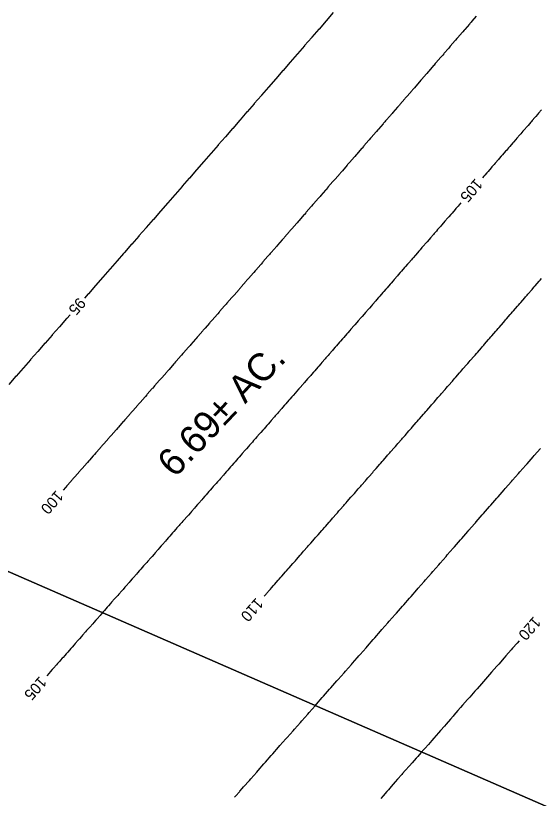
# Model space of a CAD drawing. Extents: x 1752788 to 1754108, y 472767 to 474963.
# Drawn here: x 1753161.2 to 1753208.6, y 473792.4 to 473863.1 of the extents above; entities that cross this region are included whole.
import ezdxf

# ---------------------------------------------------------------- set-up
doc = ezdxf.new("R2010")
doc.units = 0
for name, color, linetype in [('CLRLGD4', 7, 'Continuous'), ('D_Drainage_Culvert', 7, 'Continuous'), ('D_Roadway_Centerline', 7, 'Continuous'), ('Default', 7, 'Continuous'), ('S_Contours_Major', 7, 'Continuous')]:
    doc.layers.add(name, color=color, linetype=linetype)

msp = doc.modelspace()

# ---------------------------------------------------------------- linework, layer by layer
at = {"layer": 'D_Drainage_Culvert'}
msp.add_line((1753148.958, 473817.925), (1753295.6, 473753.923), dxfattribs=at)
at = {"layer": 'D_Roadway_Centerline'}
msp.add_arc((1748084.974, 477769.754), 6500, 316.3419444, 334.4169444, dxfattribs=at)
at = {"layer": 'Default'}
msp.add_line((1753295.6, 473753.923), (1753145.826, 473819.295), dxfattribs=at)
at = {"layer": 'S_Contours_Major'}
for points in [[(1753189.858, 473863.372), (1753189.219, 473862.634), (1753189.209, 473862.623), (1753188.57, 473861.886), (1753188.56, 473861.875), (1753187.921, 473861.137), (1753187.911, 473861.126), (1753187.272, 473860.388), (1753187.262, 473860.377), (1753186.623, 473859.64), (1753186.613, 473859.629), (1753185.973, 473858.892), (1753185.963, 473858.88), (1753185.324, 473858.143), (1753185.314, 473858.132), (1753184.675, 473857.395), (1753184.664, 473857.384), (1753184.025, 473856.647), (1753184.015, 473856.635), (1753183.375, 473855.899), (1753183.365, 473855.887), (1753182.725, 473855.151), (1753182.715, 473855.139), (1753182.076, 473854.404), (1753182.065, 473854.392), (1753181.454, 473853.689), (1753181.414, 473853.643), (1753180.775, 473852.909), (1753180.764, 473852.896), (1753180.125, 473852.161), (1753180.114, 473852.149), (1753179.475, 473851.414), (1753179.464, 473851.401), (1753178.824, 473850.667), (1753178.813, 473850.654), (1753178.174, 473849.92), (1753178.163, 473849.907), (1753177.523, 473849.173), (1753177.512, 473849.16), (1753176.872, 473848.426), (1753176.861, 473848.414), (1753176.222, 473847.679), (1753176.211, 473847.667), (1753175.571, 473846.933), (1753175.56, 473846.92), (1753174.919, 473846.186), (1753174.908, 473846.174), (1753174.268, 473845.44), (1753174.257, 473845.427), (1753173.617, 473844.694), (1753173.606, 473844.681), (1753172.966, 473843.948), (1753172.955, 473843.935), (1753172.314, 473843.201), (1753172.303, 473843.189), (1753171.662, 473842.456), (1753171.651, 473842.443), (1753171.012, 473841.711), (1753170.932, 473841.62), (1753170.359, 473840.964), (1753170.348, 473840.951), (1753169.707, 473840.218), (1753169.696, 473840.206), (1753169.055, 473839.473), (1753169.044, 473839.46), (1753168.403, 473838.727), (1753168.392, 473838.715), (1753167.75, 473837.982), (1753167.739, 473837.97), (1753167.402, 473837.585)], [(1753202.76, 473863.031), (1753202.375, 473862.585), (1753202.317, 473862.517), (1753202.2, 473862.382), (1753202.161, 473862.337), (1753201.726, 473861.834), (1753201.668, 473861.767), (1753201.551, 473861.632), (1753201.512, 473861.587), (1753201.077, 473861.083), (1753201.019, 473861.016), (1753200.902, 473860.881), (1753200.863, 473860.836), (1753200.424, 473860.329), (1753200.282, 473860.164), (1753200.25, 473860.127), (1753199.873, 473859.691), (1753199.844, 473859.658), (1753199.736, 473859.533), (1753199.604, 473859.38), (1753199.565, 473859.335), (1753199.13, 473858.832), (1753199.071, 473858.765), (1753198.955, 473858.63), (1753198.916, 473858.585), (1753198.48, 473858.081), (1753198.422, 473858.014), (1753198.306, 473857.88), (1753198.267, 473857.835), (1753197.831, 473857.331), (1753197.772, 473857.264), (1753197.656, 473857.13), (1753197.618, 473857.085), (1753197.181, 473856.581), (1753197.123, 473856.514), (1753197.007, 473856.38), (1753196.968, 473856.335), (1753196.531, 473855.831), (1753196.473, 473855.764), (1753196.357, 473855.63), (1753196.318, 473855.586), (1753195.881, 473855.081), (1753195.823, 473855.014), (1753195.707, 473854.88), (1753195.669, 473854.836), (1753195.231, 473854.332), (1753195.173, 473854.265), (1753195.058, 473854.131), (1753195.019, 473854.086), (1753194.581, 473853.582), (1753194.523, 473853.515), (1753194.408, 473853.381), (1753194.369, 473853.337), (1753193.931, 473852.832), (1753193.873, 473852.766), (1753193.757, 473852.632), (1753193.719, 473852.588), (1753193.281, 473852.083), (1753193.223, 473852.016), (1753193.107, 473851.883), (1753193.069, 473851.838), (1753192.63, 473851.334), (1753192.573, 473851.267), (1753192.457, 473851.134), (1753192.418, 473851.089), (1753191.98, 473850.584), (1753191.922, 473850.518), (1753191.807, 473850.385), (1753191.768, 473850.34), (1753191.329, 473849.835), (1753191.272, 473849.769), (1753191.156, 473849.636), (1753191.118, 473849.591), (1753190.679, 473849.086), (1753190.621, 473849.02), (1753190.505, 473848.887), (1753190.467, 473848.842), (1753190.027, 473848.336), (1753189.861, 473848.145), (1753189.824, 473848.102), (1753189.382, 473847.595), (1753189.353, 473847.561), (1753189.204, 473847.389), (1753189.165, 473847.345), (1753188.726, 473846.84), (1753188.668, 473846.773), (1753188.553, 473846.641), (1753188.514, 473846.596), (1753188.075, 473846.091), (1753188.017, 473846.025), (1753187.902, 473845.892), (1753187.863, 473845.848), (1753187.423, 473845.343), (1753187.366, 473845.276), (1753187.251, 473845.144), (1753187.212, 473845.1), (1753186.772, 473844.594), (1753186.714, 473844.528), (1753186.599, 473844.396), (1753186.561, 473844.352), (1753186.12, 473843.846), (1753186.063, 473843.78), (1753185.948, 473843.648), (1753185.91, 473843.604), (1753185.469, 473843.098), (1753185.411, 473843.032), (1753185.297, 473842.9), (1753185.258, 473842.856), (1753184.817, 473842.35), (1753184.76, 473842.284), (1753184.645, 473842.152), (1753184.607, 473842.108), (1753184.165, 473841.602), (1753184.108, 473841.536), (1753183.994, 473841.405), (1753183.955, 473841.361), (1753183.513, 473840.854), (1753183.456, 473840.788), (1753183.342, 473840.657), (1753183.304, 473840.613), (1753182.861, 473840.106), (1753182.804, 473840.041), (1753182.69, 473839.91), (1753182.652, 473839.866), (1753182.209, 473839.359), (1753182.152, 473839.293), (1753182.038, 473839.162), (1753182, 473839.119), (1753181.557, 473838.611), (1753181.5, 473838.546), (1753181.386, 473838.415), (1753181.348, 473838.371), (1753180.904, 473837.864), (1753180.848, 473837.798), (1753180.734, 473837.668), (1753180.696, 473837.624), (1753180.252, 473837.116), (1753180.195, 473837.051), (1753180.081, 473836.921), (1753180.043, 473836.877), (1753179.599, 473836.369), (1753179.543, 473836.304), (1753179.429, 473836.174), (1753179.391, 473836.13), (1753178.924, 473835.596), (1753178.845, 473835.506), (1753178.723, 473835.366), (1753178.689, 473835.328), (1753178.294, 473834.875), (1753178.237, 473834.81), (1753178.124, 473834.68), (1753178.086, 473834.637), (1753177.641, 473834.128), (1753177.584, 473834.063), (1753177.471, 473833.934), (1753177.433, 473833.89), (1753176.988, 473833.381), (1753176.931, 473833.317), (1753176.818, 473833.187), (1753176.78, 473833.144), (1753176.335, 473832.635), (1753176.278, 473832.57), (1753176.165, 473832.441), (1753176.127, 473832.398), (1753175.682, 473831.888), (1753175.625, 473831.824), (1753175.512, 473831.694), (1753175.474, 473831.651), (1753175.028, 473831.142), (1753174.972, 473831.077), (1753174.859, 473830.948), (1753174.821, 473830.905), (1753174.375, 473830.395), (1753174.318, 473830.331), (1753174.206, 473830.202), (1753174.168, 473830.159), (1753173.721, 473829.649), (1753173.665, 473829.585), (1753173.552, 473829.456), (1753173.515, 473829.414), (1753173.067, 473828.903), (1753173.011, 473828.839), (1753172.899, 473828.711), (1753172.861, 473828.668), (1753172.414, 473828.157), (1753172.357, 473828.093), (1753172.245, 473827.965), (1753172.208, 473827.922), (1753171.76, 473827.411), (1753171.704, 473827.347), (1753171.592, 473827.219), (1753171.554, 473827.177), (1753171.106, 473826.665), (1753171.05, 473826.601), (1753170.938, 473826.474), (1753170.9, 473826.431), (1753170.452, 473825.92), (1753170.396, 473825.856), (1753170.284, 473825.728), (1753170.247, 473825.686), (1753169.797, 473825.174), (1753169.741, 473825.11), (1753169.63, 473824.983), (1753169.593, 473824.941), (1753169.143, 473824.429), (1753169.087, 473824.365), (1753168.976, 473824.238), (1753168.939, 473824.196), (1753168.47, 473823.662), (1753168.423, 473823.609), (1753168.291, 473823.458), (1753168.18, 473823.332), (1753167.834, 473822.938), (1753167.778, 473822.875), (1753167.667, 473822.748), (1753167.63, 473822.706), (1753167.179, 473822.193), (1753167.124, 473822.13), (1753167.013, 473822.003), (1753166.976, 473821.961), (1753166.524, 473821.448), (1753166.469, 473821.385), (1753166.358, 473821.258), (1753166.321, 473821.216), (1753165.87, 473820.703), (1753165.814, 473820.64), (1753165.703, 473820.514), (1753165.667, 473820.472), (1753165.458, 473820.234)], [(1753208.664, 473854.597), (1753208.385, 473854.274), (1753208.293, 473854.167), (1753208.139, 473853.99), (1753208.047, 473853.883), (1753207.818, 473853.618), (1753207.755, 473853.545), (1753207.688, 473853.468), (1753207.44, 473853.181), (1753207.365, 473853.094), (1753207.091, 473852.778), (1753206.978, 473852.648), (1753206.79, 473852.43), (1753206.715, 473852.343), (1753206.441, 473852.027), (1753206.328, 473851.896), (1753206.14, 473851.679), (1753206.065, 473851.592), (1753205.79, 473851.275), (1753205.678, 473851.145), (1753205.49, 473850.928), (1753205.415, 473850.841), (1753205.14, 473850.524), (1753205.027, 473850.394), (1753204.84, 473850.177), (1753204.765, 473850.09), (1753204.489, 473849.773), (1753204.377, 473849.643), (1753204.189, 473849.426), (1753204.114, 473849.34), (1753203.838, 473849.021), (1753203.726, 473848.892), (1753203.539, 473848.676), (1753203.464, 473848.589), (1753203.337, 473848.443)], [(1753201.38, 473846.186), (1753201.234, 473846.018), (1753201.122, 473845.889), (1753200.935, 473845.674), (1753200.861, 473845.588), (1753200.583, 473845.267), (1753200.471, 473845.139), (1753200.284, 473844.924), (1753200.21, 473844.838), (1753199.931, 473844.517), (1753199.819, 473844.388), (1753199.633, 473844.174), (1753199.559, 473844.088), (1753199.28, 473843.767), (1753199.168, 473843.638), (1753198.982, 473843.424), (1753198.907, 473843.338), (1753198.628, 473843.016), (1753198.516, 473842.888), (1753198.33, 473842.674), (1753198.256, 473842.588), (1753197.975, 473842.264), (1753197.868, 473842.141), (1753197.689, 473841.936), (1753197.582, 473841.813), (1753197.31, 473841.5), (1753197.284, 473841.469), (1753197.064, 473841.217), (1753196.99, 473841.132), (1753196.916, 473841.046), (1753196.672, 473840.766), (1753196.561, 473840.638), (1753196.375, 473840.425), (1753196.301, 473840.34), (1753196.02, 473840.016), (1753195.909, 473839.888), (1753195.724, 473839.676), (1753195.65, 473839.59), (1753195.368, 473839.267), (1753195.257, 473839.139), (1753195.072, 473838.926), (1753194.998, 473838.841), (1753194.715, 473838.517), (1753194.605, 473838.389), (1753194.42, 473838.177), (1753194.346, 473838.092), (1753194.063, 473837.767), (1753193.952, 473837.64), (1753193.768, 473837.428), (1753193.694, 473837.343), (1753193.41, 473837.018), (1753193.3, 473836.891), (1753193.115, 473836.679), (1753193.042, 473836.594), (1753192.758, 473836.269), (1753192.647, 473836.142), (1753192.463, 473835.93), (1753192.389, 473835.846), (1753192.105, 473835.519), (1753191.995, 473835.393), (1753191.811, 473835.182), (1753191.737, 473835.097), (1753191.452, 473834.77), (1753191.342, 473834.644), (1753191.158, 473834.433), (1753191.084, 473834.349), (1753190.799, 473834.021), (1753190.689, 473833.895), (1753190.505, 473833.684), (1753190.432, 473833.6), (1753190.146, 473833.272), (1753190.036, 473833.146), (1753189.852, 473832.936), (1753189.779, 473832.852), (1753189.493, 473832.524), (1753189.383, 473832.398), (1753189.2, 473832.188), (1753189.126, 473832.104), (1753188.839, 473831.775), (1753188.73, 473831.649), (1753188.547, 473831.439), (1753188.473, 473831.356), (1753188.186, 473831.026), (1753188.076, 473830.901), (1753187.893, 473830.691), (1753187.82, 473830.608), (1753187.532, 473830.278), (1753187.423, 473830.153), (1753187.24, 473829.943), (1753187.167, 473829.86), (1753187.131, 473829.818), (1753186.834, 473829.479), (1753186.763, 473829.398), (1753186.545, 473829.147), (1753186.447, 473829.035), (1753186.225, 473828.781), (1753186.116, 473828.656), (1753185.933, 473828.448), (1753185.86, 473828.364), (1753185.571, 473828.033), (1753185.462, 473827.908), (1753185.28, 473827.7), (1753185.207, 473827.617), (1753184.917, 473827.285), (1753184.808, 473827.161), (1753184.626, 473826.953), (1753184.553, 473826.869), (1753184.517, 473826.828), (1753184.263, 473826.537), (1753184.154, 473826.413), (1753183.972, 473826.205), (1753183.9, 473826.122), (1753183.863, 473826.081), (1753183.609, 473825.79), (1753183.5, 473825.665), (1753183.318, 473825.458), (1753183.246, 473825.375), (1753183.21, 473825.333), (1753182.954, 473825.042), (1753182.846, 473824.918), (1753182.664, 473824.711), (1753182.556, 473824.586), (1753182.3, 473824.294), (1753182.191, 473824.17), (1753182.01, 473823.963), (1753181.902, 473823.839), (1753181.645, 473823.547), (1753181.537, 473823.423), (1753181.356, 473823.217), (1753181.248, 473823.093), (1753180.991, 473822.799), (1753180.882, 473822.676), (1753180.702, 473822.47), (1753180.593, 473822.346), (1753180.336, 473822.052), (1753180.228, 473821.929), (1753180.047, 473821.723), (1753179.939, 473821.599), (1753179.681, 473821.305), (1753179.573, 473821.182), (1753179.393, 473820.976), (1753179.285, 473820.853), (1753179.026, 473820.558), (1753178.918, 473820.435), (1753178.738, 473820.23), (1753178.63, 473820.107), (1753178.371, 473819.811), (1753178.263, 473819.688), (1753178.083, 473819.483), (1753177.976, 473819.36), (1753177.716, 473819.064), (1753177.608, 473818.941), (1753177.429, 473818.737), (1753177.321, 473818.614), (1753177.061, 473818.318), (1753176.953, 473818.195), (1753176.774, 473817.991), (1753176.666, 473817.868), (1753176.369, 473817.53), (1753176.279, 473817.427), (1753176.181, 473817.316), (1753176.017, 473817.128), (1753175.936, 473817.037), (1753175.748, 473816.823), (1753175.645, 473816.705), (1753175.463, 473816.498), (1753175.356, 473816.376), (1753175.094, 473816.078), (1753174.987, 473815.956), (1753174.808, 473815.753), (1753174.701, 473815.631), (1753174.438, 473815.332), (1753174.331, 473815.21), (1753174.153, 473815.007), (1753174.046, 473814.885), (1753173.782, 473814.586), (1753173.675, 473814.464), (1753173.497, 473814.261), (1753173.39, 473814.139), (1753173.126, 473813.839), (1753173.02, 473813.718), (1753172.842, 473813.515), (1753172.735, 473813.394), (1753172.47, 473813.093), (1753172.364, 473812.972), (1753172.186, 473812.77), (1753172.079, 473812.649), (1753171.814, 473812.348), (1753171.708, 473812.226), (1753171.53, 473812.025), (1753171.423, 473811.903), (1753171.158, 473811.602), (1753171.051, 473811.481), (1753170.874, 473811.279), (1753170.768, 473811.158), (1753170.501, 473810.856), (1753170.395, 473810.735), (1753170.218, 473810.534), (1753170.112, 473810.413), (1753169.845, 473810.111), (1753169.739, 473809.99), (1753169.562, 473809.789), (1753169.456, 473809.669), (1753169.188, 473809.365), (1753169.082, 473809.245), (1753168.905, 473809.044), (1753168.799, 473808.924), (1753168.532, 473808.62), (1753168.426, 473808.5), (1753168.249, 473808.299), (1753168.143, 473808.179), (1753167.875, 473807.875), (1753167.769, 473807.755), (1753167.592, 473807.554), (1753167.487, 473807.434), (1753167.218, 473807.13), (1753167.112, 473807.01), (1753166.936, 473806.81), (1753166.83, 473806.69), (1753166.561, 473806.385), (1753166.455, 473806.265), (1753166.279, 473806.065), (1753166.173, 473805.945), (1753165.882, 473805.616), (1753165.742, 473805.456), (1753165.607, 473805.304), (1753165.458, 473805.135), (1753165.394, 473805.062), (1753165.239, 473804.887), (1753165.155, 473804.791), (1753164.964, 473804.575), (1753164.858, 473804.455), (1753164.589, 473804.151), (1753164.483, 473804.031), (1753164.307, 473803.831), (1753164.201, 473803.711), (1753163.987, 473803.468)], [(1753183.63, 473810.671), (1753183.656, 473810.7), (1753183.786, 473810.848), (1753183.829, 473810.897), (1753184.103, 473811.21), (1753184.176, 473811.293), (1753184.295, 473811.429), (1753184.471, 473811.629), (1753184.558, 473811.727), (1753184.896, 473812.113), (1753184.983, 473812.212), (1753185.127, 473812.376), (1753185.213, 473812.474), (1753185.552, 473812.861), (1753185.639, 473812.959), (1753185.782, 473813.123), (1753185.869, 473813.222), (1753186.209, 473813.609), (1753186.295, 473813.707), (1753186.438, 473813.871), (1753186.524, 473813.969), (1753186.865, 473814.357), (1753186.95, 473814.455), (1753187.094, 473814.618), (1753187.179, 473814.716), (1753187.521, 473815.106), (1753187.606, 473815.203), (1753187.749, 473815.366), (1753187.834, 473815.464), (1753188.176, 473815.854), (1753188.262, 473815.951), (1753188.404, 473816.114), (1753188.49, 473816.211), (1753188.832, 473816.602), (1753188.917, 473816.7), (1753189.059, 473816.862), (1753189.144, 473816.959), (1753189.488, 473817.351), (1753189.573, 473817.448), (1753189.714, 473817.61), (1753189.799, 473817.707), (1753190.143, 473818.1), (1753190.228, 473818.197), (1753190.369, 473818.358), (1753190.454, 473818.454), (1753190.799, 473818.849), (1753190.883, 473818.945), (1753191.024, 473819.106), (1753191.109, 473819.203), (1753191.454, 473819.597), (1753191.538, 473819.694), (1753191.679, 473819.854), (1753191.763, 473819.951), (1753192.109, 473820.347), (1753192.193, 473820.443), (1753192.333, 473820.603), (1753192.417, 473820.699), (1753192.764, 473821.096), (1753192.848, 473821.192), (1753192.988, 473821.351), (1753193.072, 473821.447), (1753193.419, 473821.845), (1753193.503, 473821.941), (1753193.642, 473822.1), (1753193.726, 473822.196), (1753194.077, 473822.598), (1753194.152, 473822.683), (1753194.276, 473822.825), (1753194.35, 473822.91), (1753194.693, 473823.303), (1753194.768, 473823.389), (1753194.951, 473823.598), (1753195.034, 473823.693), (1753195.384, 473824.093), (1753195.466, 473824.188), (1753195.605, 473824.347), (1753195.688, 473824.442), (1753196.038, 473824.843), (1753196.121, 473824.938), (1753196.259, 473825.096), (1753196.341, 473825.19), (1753196.692, 473825.593), (1753196.775, 473825.687), (1753196.913, 473825.845), (1753196.995, 473825.939), (1753197.347, 473826.343), (1753197.429, 473826.437), (1753197.566, 473826.594), (1753197.649, 473826.689), (1753198.001, 473827.093), (1753198.083, 473827.187), (1753198.22, 473827.344), (1753198.302, 473827.438), (1753198.655, 473827.843), (1753198.737, 473827.937), (1753198.873, 473828.093), (1753198.955, 473828.187), (1753199.309, 473828.593), (1753199.391, 473828.687), (1753199.527, 473828.843), (1753199.608, 473828.936), (1753199.963, 473829.343), (1753200.044, 473829.437), (1753200.18, 473829.592), (1753200.261, 473829.686), (1753200.617, 473830.094), (1753200.698, 473830.187), (1753200.833, 473830.342), (1753200.914, 473830.435), (1753201.27, 473830.844), (1753201.351, 473830.937), (1753201.486, 473831.092), (1753201.567, 473831.185), (1753201.924, 473831.595), (1753202.005, 473831.688), (1753202.139, 473831.842), (1753202.22, 473831.935), (1753202.577, 473832.346), (1753202.658, 473832.438), (1753202.792, 473832.592), (1753202.873, 473832.685), (1753203.231, 473833.097), (1753203.311, 473833.189), (1753203.445, 473833.343), (1753203.525, 473833.435), (1753203.884, 473833.848), (1753203.964, 473833.94), (1753204.097, 473834.093), (1753204.177, 473834.185), (1753204.537, 473834.599), (1753204.617, 473834.691), (1753204.75, 473834.844), (1753204.83, 473834.935), (1753205.219, 473835.383), (1753205.247, 473835.416), (1753205.421, 473835.616), (1753205.497, 473835.704), (1753205.843, 473836.101), (1753205.922, 473836.193), (1753206.055, 473836.345), (1753206.134, 473836.436), (1753206.496, 473836.853), (1753206.575, 473836.944), (1753206.707, 473837.096), (1753206.786, 473837.187), (1753207.148, 473837.604), (1753207.227, 473837.695), (1753207.359, 473837.847), (1753207.438, 473837.938), (1753207.801, 473838.356), (1753207.88, 473838.446), (1753208.011, 473838.598), (1753208.09, 473838.688), (1753208.453, 473839.107), (1753208.532, 473839.198), (1753208.663, 473839.349)], [(1753166.09, 473836.086), (1753165.793, 473835.747), (1753165.782, 473835.734), (1753165.14, 473835.002), (1753165.129, 473834.99), (1753164.487, 473834.257), (1753164.477, 473834.245), (1753163.834, 473833.513), (1753163.824, 473833.5), (1753163.181, 473832.768), (1753163.171, 473832.756), (1753162.528, 473832.024), (1753162.518, 473832.012), (1753161.875, 473831.279), (1753161.864, 473831.267), (1753161.221, 473830.535), (1753161.211, 473830.523), (1753160.567, 473829.79)], [(1753180.934, 473792.5), (1753180.97, 473792.541), (1753181.057, 473792.64), (1753181.38, 473793.006), (1753181.427, 473793.059), (1753181.637, 473793.297), (1753181.755, 473793.431), (1753182.283, 473794.03), (1753182.414, 473794.178), (1753182.942, 473794.777), (1753183.072, 473794.925), (1753183.601, 473795.525), (1753183.73, 473795.671), (1753184.259, 473796.272), (1753184.388, 473796.418), (1753184.918, 473797.02), (1753185.045, 473797.165), (1753185.577, 473797.768), (1753185.703, 473797.912), (1753186.235, 473798.516), (1753186.361, 473798.659), (1753186.893, 473799.264), (1753187.018, 473799.406), (1753187.552, 473800.012), (1753187.675, 473800.153), (1753188.21, 473800.761), (1753188.333, 473800.9), (1753188.868, 473801.509), (1753188.99, 473801.648), (1753189.526, 473802.258), (1753189.647, 473802.395), (1753190.184, 473803.006), (1753190.304, 473803.143), (1753190.841, 473803.755), (1753190.96, 473803.891), (1753191.502, 473804.507), (1753191.599, 473804.618), (1753192.008, 473805.084), (1753192.032, 473805.111), (1753192.18, 473805.28), (1753192.285, 473805.4), (1753192.814, 473806.002), (1753192.942, 473806.148), (1753193.471, 473806.751), (1753193.598, 473806.896), (1753194.128, 473807.5), (1753194.254, 473807.644), (1753194.785, 473808.25), (1753194.91, 473808.393), (1753195.442, 473808.999), (1753195.566, 473809.141), (1753196.099, 473809.749), (1753196.222, 473809.89), (1753196.755, 473810.499), (1753196.878, 473810.638), (1753197.412, 473811.249), (1753197.533, 473811.387), (1753198.068, 473811.999), (1753198.189, 473812.136), (1753198.725, 473812.749), (1753198.844, 473812.885), (1753199.381, 473813.499), (1753199.499, 473813.634), (1753200.037, 473814.249), (1753200.154, 473814.383), (1753200.693, 473814.999), (1753200.809, 473815.132), (1753201.349, 473815.75), (1753201.464, 473815.882), (1753202.006, 473816.502), (1753202.108, 473816.618), (1753202.604, 473817.186), (1753202.686, 473817.28), (1753202.774, 473817.381), (1753203.316, 473818.002), (1753203.428, 473818.13), (1753203.972, 473818.753), (1753204.083, 473818.88), (1753204.627, 473819.504), (1753204.737, 473819.63), (1753205.282, 473820.255), (1753205.391, 473820.38), (1753205.938, 473821.006), (1753206.046, 473821.13), (1753206.593, 473821.758), (1753206.7, 473821.88), (1753207.248, 473822.509), (1753207.353, 473822.631), (1753207.902, 473823.261), (1753208.007, 473823.381), (1753208.557, 473824.013)], [(1753206.638, 473806.634), (1753206.461, 473806.432), (1753206.049, 473805.961), (1753205.925, 473805.819), (1753205.449, 473805.275), (1753205.29, 473805.094), (1753204.798, 473804.531), (1753204.631, 473804.34), (1753204.147, 473803.788), (1753203.971, 473803.587), (1753203.79, 473803.38), (1753203.415, 473802.953), (1753203.241, 473802.753), (1753202.843, 473802.3), (1753202.652, 473802.081), (1753202.192, 473801.556), (1753201.992, 473801.328), (1753201.54, 473800.813), (1753201.358, 473800.605), (1753201.117, 473800.331), (1753200.753, 473799.916), (1753200.67, 473799.821), (1753200.448, 473799.569), (1753200.04, 473799.104), (1753199.887, 473798.929), (1753199.54, 473798.533), (1753199.365, 473798.335), (1753198.931, 473797.84), (1753198.751, 473797.634), (1753198.442, 473797.283), (1753198.124, 473796.921), (1753198.028, 473796.812), (1753197.773, 473796.522), (1753197.483, 473796.191), (1753197.335, 473796.023), (1753196.973, 473795.611), (1753196.742, 473795.347), (1753196.355, 473794.907), (1753196.116, 473794.635), (1753196.047, 473794.558), (1753195.668, 473794.126), (1753195.457, 473793.886), (1753195.096, 473793.476), (1753194.843, 473793.188), (1753194.707, 473793.034), (1753194.362, 473792.641), (1753194.139, 473792.387)]]:
    msp.add_lwpolyline(points, dxfattribs=at)

# ---------------------------------------------------------------- texts
at = {"layer": 'CLRLGD4'}
msp.add_text('6.69± AC.', height=2.49, rotation=46.58322, dxfattribs=at).set_placement((1753175.554, 473821.272))
at = {"layer": 'S_Contours_Major'}
for s, rotation, p in [('105', 229.06867, (1753202.692, 473848.459)), ('95', 228.78964, (1753166.855, 473837.715)), ('100', 228.6573, (1753164.841, 473820.288)), ('110', 228.7002, (1753182.895, 473810.589)), ('120', 228.83438, (1753207.96, 473808.902)), ('105', 228.53651, (1753163.342, 473803.49))]:
    msp.add_text(s, height=0.996, rotation=rotation, dxfattribs=at).set_placement(p)

doc.saveas('drawing.dxf')
